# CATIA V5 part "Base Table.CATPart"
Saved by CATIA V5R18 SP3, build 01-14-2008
Part number: Moving Table Part
Bounding box of the stored display mesh (mm): x -75 to 75, y -52.5 to 52.5, z 0 to 12
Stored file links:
  E:\#00 CATIA V5 Movie\#03 CATIA V5 Data\#07 KIN\Balance Unit (1)\Base Table.CATPart
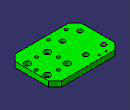
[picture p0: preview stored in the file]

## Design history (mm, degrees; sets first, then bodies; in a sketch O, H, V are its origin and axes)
Body1 "PartBody" (main body)
  Solid1: solid without history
